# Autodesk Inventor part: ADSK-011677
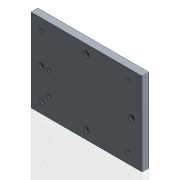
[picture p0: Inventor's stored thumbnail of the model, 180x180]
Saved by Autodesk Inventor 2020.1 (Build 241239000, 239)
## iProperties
Created: 2000-02
Part Number: ADSK-011677
Material: Pearson Aluminium
Document SubType Name: Modeling
Designer: glanglot
Density: 2.71 g/cm^3
Appearance: Pearson-Aluminum
Mass: 1027.29 g
Surface Area: 726.906 cm^2
Volume: 379.074 cm^3
Control State: 0
Checked Out: False
Master: False
Shininess: 35.0
Length Units: 11269
Angle Units: 11279
Time Units: 11290
Mass Units: 11283
Length Display Precision: 5
Angle Display Precision: 2
Compacted: True
Cutlength: 8.0
Material Desc: FLAT,ALUM,0.500X06.000
Material_Number: A084016
Dimensions: 203x152x12,5 mm
Mass: 1,027 kg
DocNumber: ADSK-011677.ipt
Folder: 01 - Themengebiete\Simplification\01 - Packaging machine\
VDS_Category: 3D Komponenten
Density: 2.71
Volumn: 386.55741498956394
Area: 731.218490334482
PropertySet Name: Model Information
Author: glanglot
Revision Number: -
Title: base plate
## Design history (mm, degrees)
node "Solide1"
  node "Extrusion1" dims "d2" = 12.5, "d3" = 0
  node "Hole2" dims "d25" = 9.92188, "d26" = 11.14425, "d27" = 6.35, "d28" = 82 deg, "d29" = 19.05, "d30" = 118 deg
  node "Hole3" dims "d31" = 10.31875, "d32" = 11.14425, "d33" = 6.35, "d34" = 82 deg, "d35" = 19.05, "d36" = 118 deg
  node "Hole4" dims "d45" = 6.74688, "d46" = 11.14425, "d47" = 6.35, "d48" = 82 deg, "d49" = 19.05, "d50" = 118 deg
  node "Hole5" dims "d55" = 6.74688, "d56" = 11.14425, "d57" = 6.35, "d58" = 82 deg, "d59" = 19.05, "d60" = 118 deg
sketch "Sketch1"
  geometry: L1 (-101.5, -76)-(101.5, -76); L2 (101.5, -76)-(101.5, 76); L3 (101.5, 76)-(-101.5, 76); L4 (-101.5, 76)-(-101.5, -76); 3 further points
  constraints: 8 end point, 2 midpoint, 2 parallel, 1 horizontal, 1 horizontal alignment, 1 perpendicular, 1 vertical alignment
  dimensions: "d0" = 152 distance between parallel lines of L1 L3; "d1" = 203 distance between parallel lines of L2 L4
sketch "Sketch3"
  geometry: L1 (0, 60)-(0, -60); L2 (-82.5, 0)-(82.5, 0); 1 further point
  constraints: 4 end point, 2 midpoint, 1 horizontal, 1 vertical
  dimensions: "d61" = 165 distance of L2.start L2.end; "d62" = 120 distance of L1.start L1.end
sketch "Sketch4"
  geometry: L1 (-101.5, -76)-(-101.5, 76) reference; L2 (-76.5, 56.5)-(81.5, 56.5); L3 (81.5, 56.5)-(81.5, -56.5); L4 (81.5, -56.5)-(-76.5, -56.5); L5 (-76.5, -56.5)-(-76.5, 56.5); 4 further points
  constraints: 8 end point, 2 coincident, 2 midpoint, 2 parallel, 1 horizontal, 1 horizontal alignment, 1 perpendicular
  dimensions: "d63" = 158 distance of L2.start L2.end; "d64" = 113 distance of L2.end L3.end; "d65" = 25 distance between parallel lines of L1 L5
sketch "Sketch5"
  geometry: L1 (101.5, -76)-(-101.5, -76) reference; L2 (101.5, 76)-(101.5, -76) reference; L3 (68.5, 0)-(68.5, -41)
  constraints: 2 end point, 1 vertical
  dimensions: "d53" = 41 distance of L3.end L3.start; "d54" = 35 distance from line of L1 L3.end; "d66" = 33 distance between parallel lines of L2 L3
node "Corps solides"
node "Corps surfaciques"
